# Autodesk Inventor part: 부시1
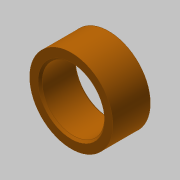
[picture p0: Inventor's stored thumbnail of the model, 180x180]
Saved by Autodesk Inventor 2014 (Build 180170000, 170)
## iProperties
Created: 2016-08
Part Number: 부시1
Material: 강철, 탄소
Document SubType Name: Modeling
Designer: mduedu
Density: 7.87 g/cm^3
Appearance: 주황색
Author: mduedu
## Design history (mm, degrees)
sketch "스케치1"
  geometry: C1 r 7.5 at (0, 0); C2 r 10 at (0, 0); 1 further point
  constraints: 2 centre point, 2 coincident
  dimensions: "d0" = 15 diameter of C1; "d1" = 20 diameter of C2
extrude "돌출1" new body sketch "스케치1" stored distance "d2" = 9; taper "d3" = 0 deg
chamfer "모따기1" distance "d4" = 0.5; stored, may be unused: second distance "d5" = 2, angle "d6" = 45 deg
node "솔리드1"
